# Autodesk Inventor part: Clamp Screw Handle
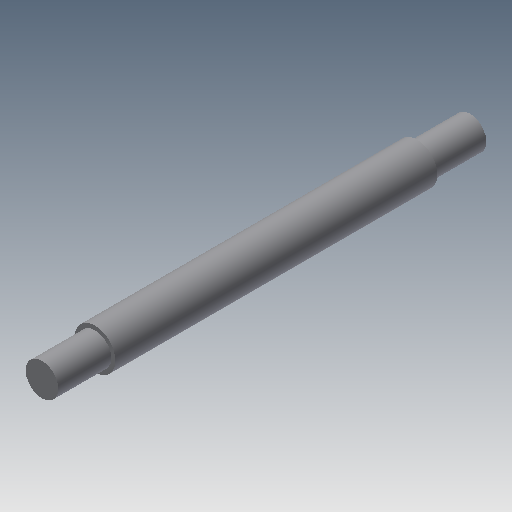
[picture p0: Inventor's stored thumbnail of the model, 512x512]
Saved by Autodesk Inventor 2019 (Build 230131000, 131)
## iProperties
Shininess: 77.0
Length Units: 11269
Angle Units: 11279
Time Units: 11290
Mass Units: 11283
Length Display Precision: 3
Angle Display Precision: 2
Compacted: True
Created: 2002-02
Part Number: Clamp Screw Handle
Document SubType Name: Modeling
Designer: ***
Density: 1 g/cm^3
Material: Generic
Mass: 7.51155 g
Surface Area: 32.9239 cm^2
Volume: 7.51155 cm^3
Appearance: Default
Density: 0.0
Volumn: 0.0
Area: 0.0
PropertySet Name: Model Information
Control State: 0
Master: False
Checked Out: False
Author: ***
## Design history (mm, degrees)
sketch "Sketch1"
  geometry: L1 (0, 105)-(4, 105); L2 (4, 105)-(4, 92); L3 (4, 92)-(5, 92); L4 (5, 92)-(5, 13); L5 (5, 13)-(4, 13); L6 (4, 13)-(4, 0); L7 (4, 0)-(0, 0); L8 (0, 0)-(0, 105)
  constraints: 16 end point, 5 parallel, 2 equal length, 1 collinear, 1 horizontal, 1 perpendicular
  dimensions: "d0" = 10 diameter of L4 L8; "d1" = 8 diameter of L2 L8; "d2" = 13 distance of L1.end L2.end; "d3" = 79 distance of L3.end L4.end
revolve "Revolution1" sketch "Sketch1" stored, may be unused: angle "d4" = 90 deg
body "Solid1"
